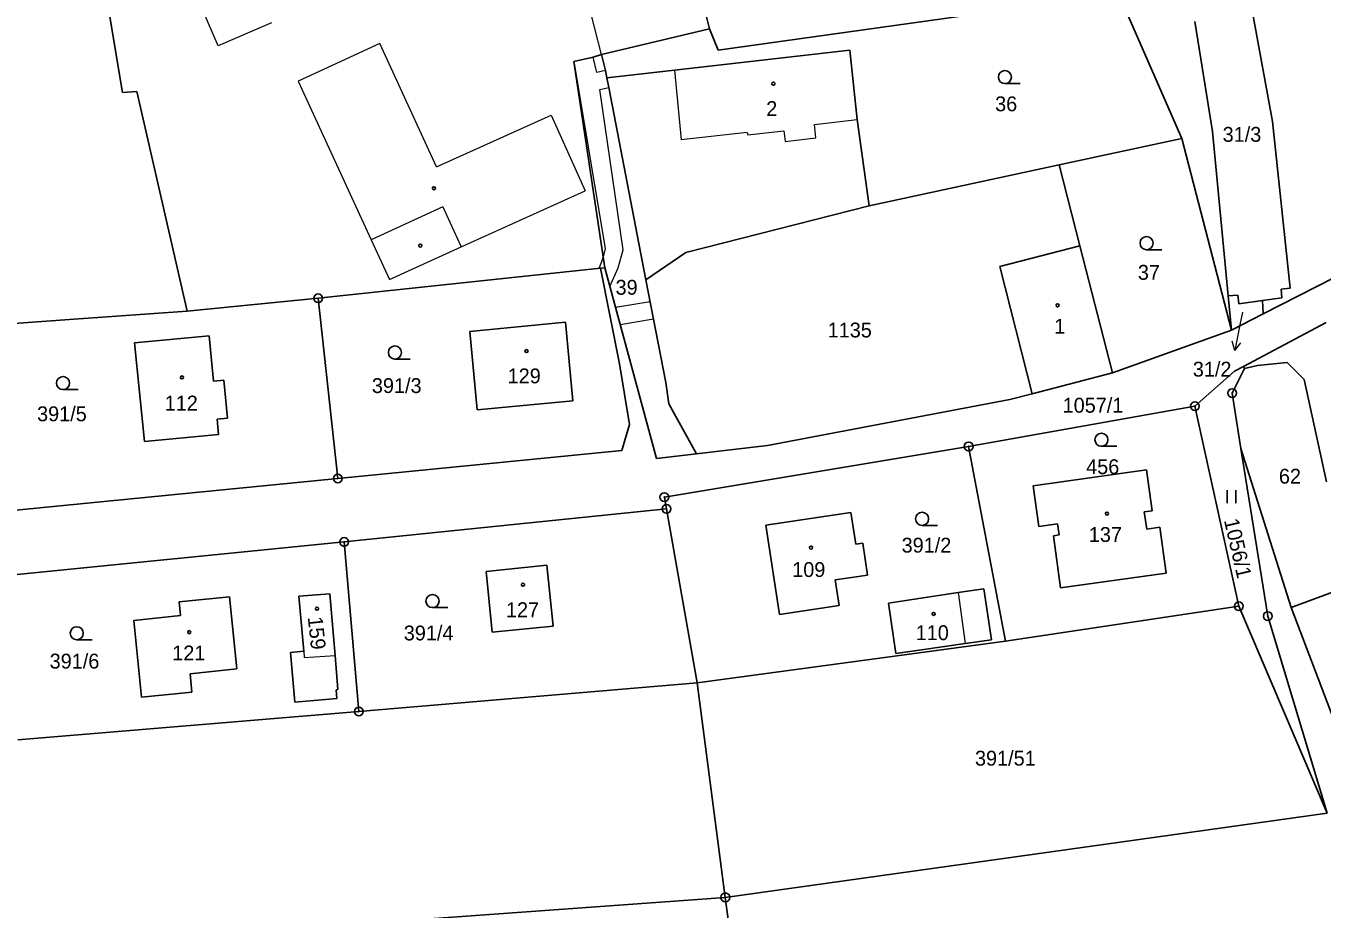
# Model space of a CAD drawing. Extents: x -618848 to -615803, y -1044450 to -1042254.
# Drawn here: x -617078.1 to -616929.8, y -1043345.1 to -1043244.1 of the extents above; entities that cross this region are included whole.
import ezdxf
from ezdxf.enums import TextEntityAlignment as Align

# ---------------------------------------------------------------- set-up
doc = ezdxf.new("R2010")
doc.units = 0
doc.header["$LTSCALE"] = 0.68
for name, color, linetype, lineweight in [('1', 7, 'Continuous', 25), ('13', 7, 'Continuous', 13), ('3', 7, 'Continuous', 25), ('4', 7, 'Continuous', 13), ('5', 7, 'Continuous', 25), ('7', 7, 'Continuous', 13), ('8', 7, 'Continuous', 25)]:
    doc.layers.add(name, color=color, linetype=linetype, lineweight=lineweight)
doc.layers.add('2', color=7, linetype='Continuous')

msp = doc.modelspace()

# ---------------------------------------------------------------- linework, layer by layer
at = {"layer": '1'}
for p, q in [((-617071.44, -1043225.27), (-617067.07, -1043251.7)), ((-616999.87, -1043244.41), (-617001.43, -1043238.1)), ((-616953.81, -1043238.68), (-616945.8, -1043256.94)), ((-616998.89, -1043246.85), (-616960.17, -1043241.44)), ((-616944.31, -1043243.57), (-616942.31, -1043256.16)), ((-616937.69, -1043242.72), (-616935.42, -1043255.02)), ((-617012.23, -1043247.36), (-616999.87, -1043244.41)), ((-616999.87, -1043244.41), (-616998.89, -1043246.85)), ((-616983.82, -1043246.85), (-617003.89, -1043249.14)), ((-616983.82, -1043246.85), (-616982.98, -1043254.77)), ((-617015.4, -1043248.16), (-617013.18, -1043247.64)), ((-617011.87, -1043271.75), (-617015.4, -1043248.16)), ((-617013.18, -1043247.64), (-617012.23, -1043247.36)), ((-617012.23, -1043247.36), (-617011.77, -1043249.17)), ((-617011.77, -1043249.17), (-617011.61, -1043250.02)), ((-617003.89, -1043249.14), (-617011.61, -1043250.02)), ((-617011.61, -1043250.02), (-617011.39, -1043251.14)), ((-617011.39, -1043251.14), (-617007.15, -1043273.12)), ((-617067.07, -1043251.7), (-617065.4, -1043251.58)), ((-617059.66, -1043276.7), (-617065.4, -1043251.58)), ((-616982.98, -1043254.77), (-616981.58, -1043264.66)), ((-616935.42, -1043255.02), (-616933.42, -1043274.08)), ((-616959.86, -1043259.97), (-616945.8, -1043256.94)), ((-616945.8, -1043256.94), (-616940.11, -1043278.89)), ((-616942.31, -1043256.16), (-616940.49, -1043274.95)), ((-616981.58, -1043264.66), (-616959.86, -1043259.97)), ((-616959.86, -1043259.97), (-616957.48, -1043269.23)), ((-616904.84, -1043260.79), (-616936.5, -1043277.03)), ((-617002.58, -1043269.99), (-616981.58, -1043264.66)), ((-616966.63, -1043271.59), (-616957.48, -1043269.23)), ((-616957.48, -1043269.23), (-616953.74, -1043283.77)), ((-617007.15, -1043273.12), (-617002.58, -1043269.99)), ((-617012.36, -1043271.8), (-617044.67, -1043275.24)), ((-617012.36, -1043271.8), (-617011.87, -1043271.75)), ((-617010.19, -1043282.73), (-617012.36, -1043271.8)), ((-617011.87, -1043271.75), (-617005.95, -1043293.58)), ((-616966.63, -1043271.59), (-616962.96, -1043286.16)), ((-617007.15, -1043273.12), (-617004.87, -1043284.87)), ((-617059.66, -1043276.7), (-617044.67, -1043275.24)), ((-617042.41, -1043295.86), (-617044.67, -1043275.24)), ((-616940.49, -1043274.95), (-616939.42, -1043274.88)), ((-616940.49, -1043274.95), (-616940.11, -1043278.89)), ((-616939.29, -1043275.87), (-616939.42, -1043274.88)), ((-616936.59, -1043275.51), (-616934.35, -1043275.2)), ((-616934.46, -1043274.21), (-616933.42, -1043274.08)), ((-616934.35, -1043275.2), (-616934.46, -1043274.21)), ((-616939.29, -1043275.87), (-616936.59, -1043275.51)), ((-616936.59, -1043275.51), (-616936.5, -1043277.03)), ((-617016.35, -1043277.99), (-617027.3, -1043279.03)), ((-617015.5, -1043286.96), (-617016.35, -1043277.99)), ((-616936.5, -1043277.03), (-616940.11, -1043278.89)), ((-616938.76, -1043283.04), (-616929.31, -1043278.03)), ((-617065.68, -1043280.33), (-617057.12, -1043279.53)), ((-617057.12, -1043279.53), (-617056.66, -1043284.71)), ((-617027.3, -1043279.03), (-617026.45, -1043288)), ((-616940.11, -1043278.89), (-616953.74, -1043283.77)), ((-617064.54, -1043291.64), (-617065.68, -1043280.33)), ((-616933.76, -1043282.59), (-616937.16, -1043282.93)), ((-616931.81, -1043284.55), (-616933.76, -1043282.59)), ((-617009.04, -1043289.68), (-617010.19, -1043282.73)), ((-616944.31, -1043287.59), (-616939.77, -1043283.57)), ((-616938.64, -1043283.27), (-616940.05, -1043286.09)), ((-616939.77, -1043283.57), (-616938.76, -1043283.04)), ((-616938.76, -1043283.04), (-616938.64, -1043283.27)), ((-616937.16, -1043282.93), (-616938.64, -1043283.27)), ((-617056.66, -1043284.71), (-617055.47, -1043284.63)), ((-617055.47, -1043284.63), (-617055.05, -1043288.97)), ((-617004.87, -1043284.87), (-617004.51, -1043287.34)), ((-616931.81, -1043284.55), (-616929.24, -1043296.24)), ((-617026.45, -1043288), (-617015.5, -1043286.96)), ((-616965.48, -1043286.81), (-616993.22, -1043292.08)), ((-616940.05, -1043286.09), (-616939.04, -1043292.44)), ((-617004.51, -1043287.34), (-617001.37, -1043293.03)), ((-616970.21, -1043292.19), (-616944.31, -1043287.59)), ((-616944.31, -1043287.59), (-616939.28, -1043310.49)), ((-617055.05, -1043288.97), (-617056.24, -1043289.07)), ((-617056.24, -1043289.07), (-617056.08, -1043290.83)), ((-617009.9, -1043292.67), (-617009.04, -1043289.68)), ((-617056.08, -1043290.83), (-617064.54, -1043291.64)), ((-617042.41, -1043295.86), (-617009.9, -1043292.67)), ((-617001.37, -1043293.03), (-617005.95, -1043293.58)), ((-616970.21, -1043292.19), (-617005.04, -1043298)), ((-617000.4, -1043292.91), (-617001.37, -1043293.03)), ((-617000.4, -1043292.91), (-616993.22, -1043292.08)), ((-616965.98, -1043314.49), (-616970.21, -1043292.19)), ((-616939.04, -1043292.44), (-616935.98, -1043311.61)), ((-616933.31, -1043310.62), (-616939.04, -1043292.44)), ((-617081.2, -1043299.68), (-617042.41, -1043295.86)), ((-616949.84, -1043294.89), (-616962.83, -1043296.69)), ((-616949.19, -1043299.55), (-616949.84, -1043294.89)), ((-616962.83, -1043296.69), (-616962.17, -1043301.35)), ((-617004.8, -1043299.35), (-617005.04, -1043298)), ((-617004.8, -1043299.35), (-617041.69, -1043303.13)), ((-617004.8, -1043299.35), (-617001.29, -1043319.26)), ((-616983.69, -1043299.74), (-616993.41, -1043301.2)), ((-616983.11, -1043303.39), (-616983.69, -1043299.74)), ((-616950.12, -1043299.67), (-616949.19, -1043299.55)), ((-616949.82, -1043301.66), (-616950.12, -1043299.67)), ((-616993.41, -1043301.2), (-616991.85, -1043311.43)), ((-616962.17, -1043301.35), (-616960.04, -1043301.04)), ((-616960.04, -1043301.04), (-616959.86, -1043302.32)), ((-616948.34, -1043301.44), (-616949.82, -1043301.66)), ((-616947.6, -1043306.69), (-616948.34, -1043301.44)), ((-617041.69, -1043303.13), (-617080.65, -1043307.01)), ((-617041.69, -1043303.13), (-617040.01, -1043322.53)), ((-616983.11, -1043303.39), (-616982.33, -1043303.28)), ((-616982.33, -1043303.28), (-616981.78, -1043306.91)), ((-616959.86, -1043302.32), (-616960.51, -1043302.43)), ((-616960.51, -1043302.43), (-616959.68, -1043308.38)), ((-617025.43, -1043306.49), (-617018.48, -1043305.79)), ((-617018.48, -1043305.79), (-617017.78, -1043312.75)), ((-617024.74, -1043313.45), (-617025.43, -1043306.49)), ((-616985.47, -1043307.45), (-616983.62, -1043307.18)), ((-616985.04, -1043310.41), (-616985.47, -1043307.45)), ((-616981.78, -1043306.91), (-616983.62, -1043307.18)), ((-616959.68, -1043308.38), (-616947.6, -1043306.69)), ((-617043.33, -1043309.05), (-617046.86, -1043309.33)), ((-617046.86, -1043309.33), (-617046.31, -1043315.61)), ((-617042.73, -1043316.12), (-617043.33, -1043309.05)), ((-616976.42, -1043309.69), (-616971.43, -1043308.93)), ((-616968.49, -1043308.48), (-616971.43, -1043308.93)), ((-616967.58, -1043314.32), (-616968.49, -1043308.48)), ((-616933.31, -1043310.62), (-616928.44, -1043308.83)), ((-617054.81, -1043309.4), (-617060.56, -1043309.99)), ((-617060.56, -1043309.99), (-617060.41, -1043311.55)), ((-617053.98, -1043317.66), (-617054.81, -1043309.4)), ((-616991.85, -1043311.43), (-616985.04, -1043310.41)), ((-616976.42, -1043309.69), (-616979.37, -1043310.14)), ((-616979.37, -1043310.14), (-616978.55, -1043315.91)), ((-616939.28, -1043310.49), (-616965.98, -1043314.49)), ((-616929.18, -1043334.15), (-616939.28, -1043310.49)), ((-616933.31, -1043310.62), (-616920.31, -1043344.84)), ((-617060.41, -1043311.55), (-617065.75, -1043312.13)), ((-617065.75, -1043312.13), (-617064.87, -1043320.89)), ((-616929.18, -1043334.15), (-616935.98, -1043311.61)), ((-617017.78, -1043312.75), (-617024.74, -1043313.45)), ((-616965.98, -1043314.49), (-617001.29, -1043319.26)), ((-616970.6, -1043314.76), (-616975.59, -1043315.48)), ((-616970.6, -1043314.76), (-616967.58, -1043314.32)), ((-617047.82, -1043315.76), (-617046.31, -1043315.61)), ((-617047.33, -1043321.45), (-617047.82, -1043315.76)), ((-617042.41, -1043320.03), (-617042.73, -1043316.12)), ((-616978.55, -1043315.91), (-616975.59, -1043315.48)), ((-617059.31, -1043318.21), (-617053.98, -1043317.66)), ((-617059.11, -1043320.32), (-617059.31, -1043318.21)), ((-617040.01, -1043322.53), (-617001.29, -1043319.26)), ((-617001.29, -1043319.26), (-616998.06, -1043343.8)), ((-617064.87, -1043320.89), (-617059.11, -1043320.32)), ((-617042.54, -1043321.06), (-617047.33, -1043321.45)), ((-617042.62, -1043320.05), (-617042.41, -1043320.03)), ((-617042.54, -1043321.06), (-617042.62, -1043320.05)), ((-617079.03, -1043325.79), (-617040.01, -1043322.53)), ((-616998.06, -1043343.8), (-616929.18, -1043334.15)), ((-617114.36, -1043352.18), (-616998.06, -1043343.8)), ((-616998.06, -1043343.8), (-616994.86, -1043368.03))]:
    msp.add_line(p, q, dxfattribs=at)
for points in [[(-617082.66, -1043278.34), (-617072.59, -1043277.62), (-617059.66, -1043276.7)], [(-616965.48, -1043286.81), (-616962.96, -1043286.16), (-616953.74, -1043283.77)]]:
    msp.add_lwpolyline(points, dxfattribs=at)
at = {"layer": '13'}
for points in [[(-617011.27, -1043273.88), (-617010.32, -1043271.76), (-617009.77, -1043269.68), (-617012.42, -1043251.34), (-617011.39, -1043251.14), (-617011.61, -1043250.02), (-617011.77, -1043249.17), (-617012.78, -1043249.39), (-617013.18, -1043247.64), (-617015.4, -1043248.16), (-617011.81, -1043269.56), (-617012.06, -1043270.49), (-617011.87, -1043271.75), (-617011.24, -1043274.06)], [(-617012.54, -1043271.82), (-617012.36, -1043271.8), (-617011.87, -1043271.75), (-617012.06, -1043270.49), (-617012.22, -1043271.09)], [(-617010.11, -1043278.23), (-617006.28, -1043277.59), (-617006.66, -1043275.63), (-617010.64, -1043276.29)]]:
    msp.add_lwpolyline(points, close=True, dxfattribs=at)
at = {"layer": '3'}
for p, q in [((-616966.063, -1043250.68), (-616964.313, -1043250.68)), ((-616949.843, -1043269.68), (-616948.093, -1043269.68)), ((-617035.873, -1043282.2), (-617034.123, -1043282.2)), ((-617073.863, -1043285.7), (-617072.113, -1043285.7)), ((-616955.013, -1043292.18), (-616953.263, -1043292.18)), ((-616940.631, -1043298.69), (-616940.631, -1043297.19)), ((-616939.63, -1043298.69), (-616939.63, -1043297.19)), ((-616975.543, -1043301.23), (-616973.793, -1043301.23)), ((-617031.573, -1043310.64), (-617029.823, -1043310.64)), ((-617072.293, -1043314.33), (-617070.543, -1043314.33))]:
    msp.add_line(p, q, dxfattribs=at)
for centre in [(-616966.0629, -1043249.9298), (-616949.8429, -1043268.9298), (-617035.8729, -1043281.4498), (-617073.8629, -1043284.9498), (-616955.0129, -1043291.4298), (-616975.5429, -1043300.4798), (-617031.5729, -1043309.8898), (-617072.2929, -1043313.5798)]:
    msp.add_circle(centre, 0.75, dxfattribs=at)
at = {"layer": '4'}
for p, q in [((-617012.23, -1043247.36), (-617013.83, -1043241.04)), ((-617056.1, -1043246.37), (-617057.95, -1043242.12)), ((-617050, -1043243.74), (-617056.1, -1043246.37)), ((-617037.6, -1043246.08), (-617046.96, -1043250.39)), ((-617031.1, -1043260.21), (-617037.6, -1043246.08)), ((-617003.89, -1043249.14), (-617003.11, -1043257.1)), ((-617046.96, -1043250.39), (-617038.59, -1043268.56)), ((-616987.84, -1043255.37), (-616982.98, -1043254.77)), ((-616987.71, -1043256.9), (-616987.84, -1043255.37)), ((-616995.55, -1043256.27), (-617003.11, -1043257.1)), ((-616995.55, -1043256.27), (-616995.5, -1043256.54)), ((-616995.5, -1043256.54), (-616991.37, -1043256.07)), ((-616991.37, -1043256.07), (-616991.22, -1043257.29)), ((-616991.22, -1043257.29), (-616987.71, -1043256.9)), ((-617028.3, -1043269.37), (-617014.09, -1043262.93)), ((-617030.38, -1043264.78), (-617038.59, -1043268.56)), ((-617030.38, -1043264.78), (-617028.3, -1043269.37)), ((-617038.59, -1043268.56), (-617036.51, -1043273.1)), ((-617036.51, -1043273.1), (-617028.3, -1043269.37)), ((-616971.43, -1043308.93), (-616970.6, -1043314.76)), ((-617046.31, -1043315.61), (-617046.25, -1043316.34)), ((-617046.25, -1043316.34), (-617042.73, -1043316.12))]:
    msp.add_line(p, q, dxfattribs=at)
msp.add_lwpolyline([(-617031.1, -1043260.21), (-617018.01, -1043254.28), (-617014.09, -1043262.93)], dxfattribs=at)
at = {"layer": '5'}
for centre in [(-616992.5568, -1043250.6892), (-617031.4068, -1043262.6492), (-617032.9768, -1043269.2192), (-616960.0368, -1043276.0492), (-617020.8168, -1043281.2892), (-617060.2468, -1043284.2992), (-616954.3868, -1043299.8892), (-616988.2468, -1043303.7792), (-617021.2268, -1043308.0192), (-617044.7968, -1043310.7692), (-616974.2168, -1043311.3592), (-617059.4168, -1043313.4492)]:
    msp.add_circle(centre, 0.175, dxfattribs=at)
at = {"layer": '7'}
msp.add_line((-616939.733, -1043281.216), (-616939.05, -1043280.328), dxfattribs=at)
msp.add_lwpolyline([(-616938.87, -1043276.83), (-616939.16, -1043278.27), (-616939.733, -1043281.216), (-616940.033, -1043280.137)], dxfattribs=at)
at = {"layer": '8'}
for centre, radius in [((-617044.67, -1043275.2399), 0.5), ((-617044.67, -1043275.2399), 0.0303), ((-616940.05, -1043286.0899), 0.5), ((-616944.31, -1043287.5899), 0.5), ((-616940.05, -1043286.0899), 0.0303), ((-616944.31, -1043287.5899), 0.0303), ((-616970.21, -1043292.1899), 0.5), ((-616970.21, -1043292.1899), 0.0303), ((-617042.41, -1043295.8599), 0.5), ((-617042.41, -1043295.8599), 0.0303), ((-617005.04, -1043297.9999), 0.5), ((-617004.8, -1043299.3499), 0.5), ((-617005.04, -1043297.9999), 0.0303), ((-617004.8, -1043299.3499), 0.0303), ((-617041.69, -1043303.1299), 0.5), ((-617041.69, -1043303.1299), 0.0303), ((-616939.28, -1043310.4899), 0.5), ((-616939.28, -1043310.4899), 0.0303), ((-616935.98, -1043311.6099), 0.5), ((-616935.98, -1043311.6099), 0.0303), ((-617040.01, -1043322.5299), 0.5), ((-617040.01, -1043322.5299), 0.0303), ((-616998.06, -1043343.7999), 0.5), ((-616998.06, -1043343.7999), 0.0303)]:
    msp.add_circle(centre, radius, dxfattribs=at)

# ---------------------------------------------------------------- texts
at = {"layer": '2'}
for s, p in [('2', (-616992.75, -1043254.385)), ('36', (-616965.919, -1043253.845)), ('31/3', (-616938.929, -1043257.335)), ('37', (-616949.579, -1043273.125)), ('39', (-617009.359, -1043274.835)), ('1135', (-616983.82, -1043279.725)), ('1', (-616959.79, -1043279.295)), ('129', (-617021.079, -1043284.975)), ('391/3', (-617035.67, -1043286.085)), ('112', (-617060.329, -1043288.085)), ('1057/1', (-616955.98, -1043288.335)), ('391/5', (-617073.99, -1043289.315)), ('456', (-616954.869, -1043295.365)), ('62', (-616933.439, -1043296.455)), ('137', (-616954.559, -1043303.125)), ('391/2', (-616975.04, -1043304.345)), ('109', (-616988.509, -1043307.135)), ('127', (-617021.269, -1043311.735)), ('391/4', (-617032.02, -1043314.395)), ('110', (-616974.379, -1043314.365)), ('121', (-617059.469, -1043316.685)), ('391/6', (-617072.55, -1043317.615)), ('391/51', (-616966.01, -1043328.725))]:
    msp.add_text(s, height=1.7, dxfattribs=at).set_placement(p, align=Align.CENTER)
msp.add_text('31/2', height=1.7, dxfattribs=at).set_placement((-616940.129, -1043284.205), align=Align.RIGHT)
for s, rotation, p in [('1056/1', 283, (-616940.2208, -1043304.0328)), ('159', 276, (-617045.6576, -1043313.6387))]:
    msp.add_text(s, height=1.7, rotation=rotation, dxfattribs=at).set_placement(p, align=Align.CENTER)

doc.saveas('drawing.dxf')
